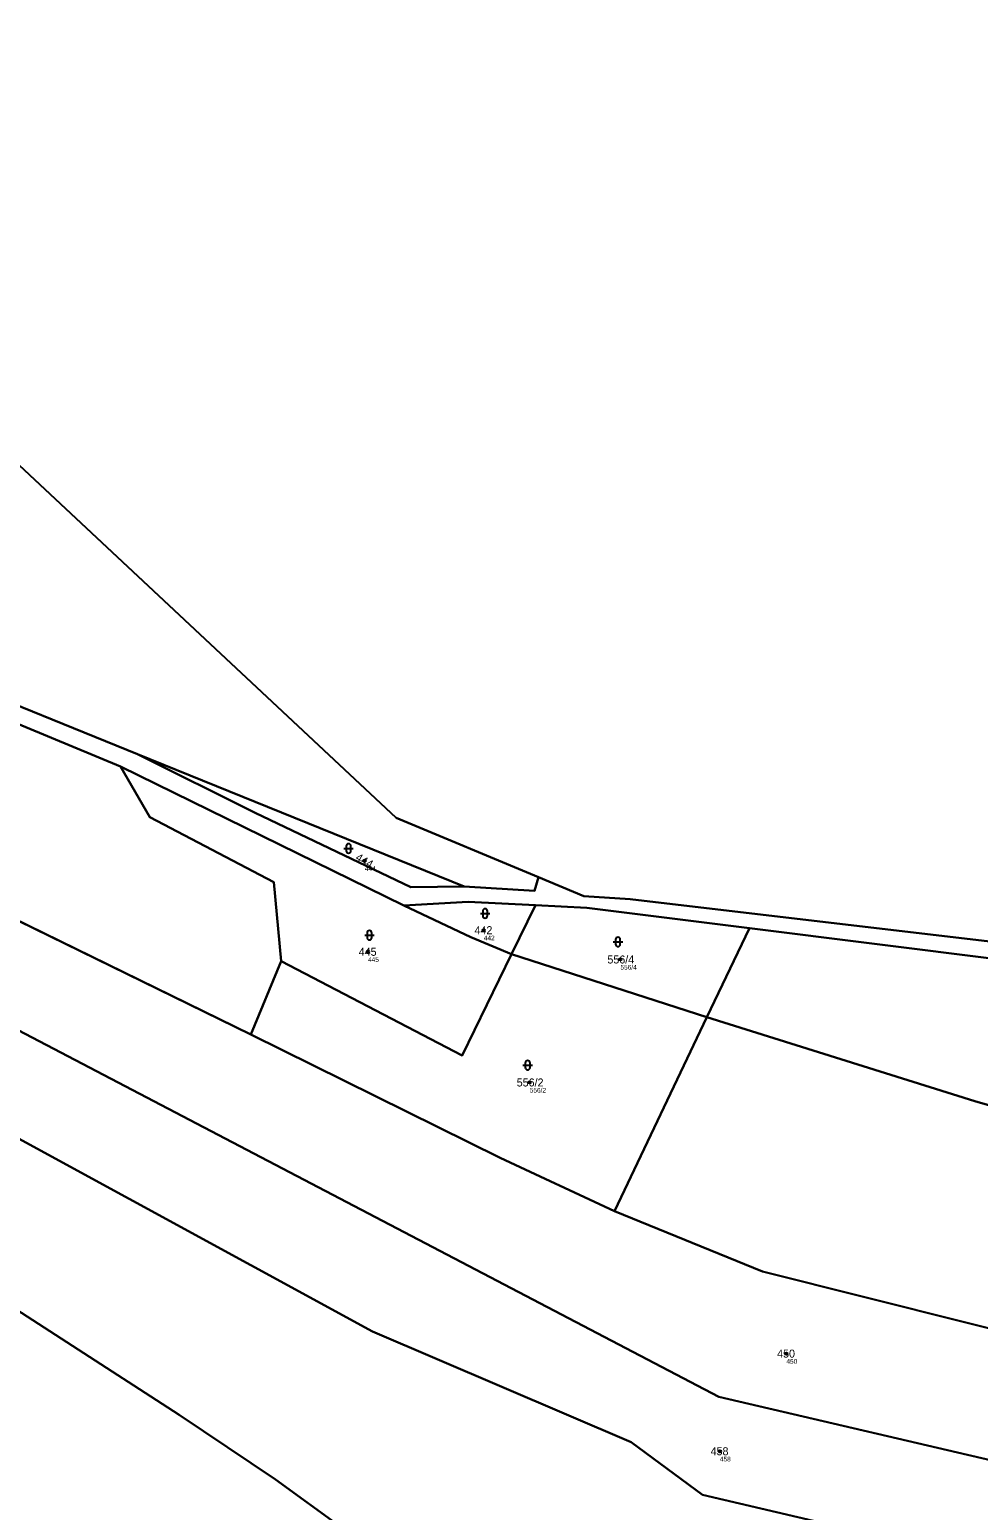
# Model space of a CAD drawing. Extents: x -766177 to -763254, y -1057727 to -1053915.
# Drawn here: x -765094.3 to -764892.9, y -1055503.5 to -1055189 of the extents above; entities that cross this region are included whole.
import ezdxf

# ---------------------------------------------------------------- set-up
doc = ezdxf.new("R2010")
doc.units = 0
for name, color, linetype in [('Vrstva 1', 7, 'Continuous'), ('Vrstva 2', 7, 'Continuous'), ('Vrstva 3', 7, 'Continuous'), ('Vrstva 50', 7, 'Continuous'), ('Vrstva 51', 7, 'Continuous')]:
    doc.layers.add(name, color=color, linetype=linetype)

msp = doc.modelspace()

# ---------------------------------------------------------------- linework, layer by layer
at = {"layer": 'Vrstva 1'}
for p, q in [((-765071.41, -1055342.94), (-765002.04, -1055371.04)), ((-765014.85, -1055375.09), (-765075.02, -1055345.53)), ((-765047.37, -1055402.44), (-765159.08, -1055347.83)), ((-764991.99, -1055385.41), (-764986.9, -1055375.01)), ((-764941.5, -1055379.87), (-764950.52, -1055398.79)), ((-764888.42, -1055386.56), (-764941.5, -1055379.87)), ((-765047.37, -1055402.44), (-765040.94, -1055386.85)), ((-764950.52, -1055398.79), (-764991.99, -1055385.41)), ((-764950.52, -1055398.79), (-764970.17, -1055440.01))]:
    msp.add_line(p, q, dxfattribs=at)
for points in [[(-764986.29, -1055369.06), (-765016.52, -1055356.43), (-765143.75, -1055237.44), (-765170.76, -1055189.03), (-765184.5, -1055172.38), (-765231.58, -1055139.36), (-765234.73, -1055135.28)], [(-764986.29, -1055369.06), (-764976.69, -1055373.07), (-764966.84, -1055373.68), (-764889.25, -1055382.83), (-764853.72, -1055377.3), (-764836.18, -1055369.38), (-764807.82, -1055352.16), (-764775.46, -1055335.75), (-764743.7, -1055324.71), (-764709.55, -1055320.26), (-764653.85, -1055301.47), (-764629.24, -1055298.84), (-764551.53, -1055278.17), (-764464.27, -1055256.83), (-764428.59, -1055244.07), (-764351.18, -1055228.58), (-764323.83, -1055218.78), (-764312.5, -1055208.03), (-764270.81, -1055152.22)], [(-765222.34, -1055253.9), (-765204.91, -1055262.89), (-765164.76, -1055294.86), (-765151.56, -1055297.73), (-765111.93, -1055326.52), (-765071.41, -1055342.94)], [(-765075.02, -1055345.53), (-765115.26, -1055328.82), (-765152.69, -1055301.94)], [(-765071.41, -1055342.94), (-765046.44, -1055355.41), (-765013.41, -1055371.14), (-765002.04, -1055371.04)], [(-765075.02, -1055345.53), (-765068.82, -1055356.3), (-765042.51, -1055370.1), (-765040.94, -1055386.85)], [(-765160.62, -1055368.14), (-764948, -1055479.38), (-764883.67, -1055494.44), (-764811.91, -1055508.77), (-764753.73, -1055525)], [(-765002.04, -1055371.04), (-764987.12, -1055371.96), (-764986.29, -1055369.06)], [(-764986.9, -1055375.01), (-765001.24, -1055374.3), (-765014.85, -1055375.09)], [(-765014.85, -1055375.09), (-765000.68, -1055381.77), (-764991.99, -1055385.41)], [(-764941.5, -1055379.87), (-764976.01, -1055375.55), (-764986.9, -1055375.01)], [(-765040.94, -1055386.85), (-765002.5, -1055406.89), (-764991.99, -1055385.41)], [(-765150.71, -1055395.09), (-765021.52, -1055465.51), (-764966.65, -1055489.05), (-764951.49, -1055500.21), (-764771.73, -1055542.36), (-764763.19, -1055547.21)], [(-764730.92, -1055455.55), (-764829.15, -1055435.06), (-764893.68, -1055416.62), (-764950.52, -1055398.79)], [(-764970.17, -1055440.01), (-764994.42, -1055428.64), (-765047.37, -1055402.44)], [(-764743.22, -1055501.86), (-764938.76, -1055452.8), (-764970.17, -1055440.01)], [(-765110.33, -1055452.36), (-765062.6, -1055483.25), (-765042.11, -1055496.97), (-765013.65, -1055517.61)]]:
    msp.add_lwpolyline(points, dxfattribs=at)
at = {"layer": 'Vrstva 3'}
for p, q in [((-765027.621, -1055362.941), (-765025.619, -1055362.941)), ((-765027.121, -1055362.441), (-765027.121, -1055363.442)), ((-765026.119, -1055363.442), (-765026.119, -1055362.441)), ((-764998.621, -1055376.731), (-764996.619, -1055376.731)), ((-764998.121, -1055376.231), (-764998.121, -1055377.232)), ((-764997.119, -1055377.232), (-764997.119, -1055376.231)), ((-765023.171, -1055381.381), (-765021.169, -1055381.381)), ((-765022.671, -1055380.881), (-765022.671, -1055381.882)), ((-765021.669, -1055381.882), (-765021.669, -1055380.881)), ((-764970.421, -1055382.791), (-764968.419, -1055382.791)), ((-764969.921, -1055382.291), (-764969.921, -1055383.292)), ((-764968.919, -1055383.292), (-764968.919, -1055382.291)), ((-764989.591, -1055408.991), (-764987.589, -1055408.991)), ((-764989.091, -1055408.491), (-764989.091, -1055409.492)), ((-764988.089, -1055409.492), (-764988.089, -1055408.491))]:
    msp.add_line(p, q, dxfattribs=at)
for centre, start, end in [((-765026.62, -1055362.4409), 0, 180), ((-765026.62, -1055363.4409), 180, 359.9878861), ((-764997.62, -1055376.2309), 0, 180), ((-764997.62, -1055377.2309), 180, 359.9878861), ((-765022.17, -1055380.8809), 0, 180), ((-765022.17, -1055381.8809), 180, 359.9878861), ((-764969.42, -1055382.2909), 0, 180), ((-764969.42, -1055383.2909), 180, 359.9878861), ((-764988.59, -1055408.4909), 0, 180), ((-764988.59, -1055409.4909), 180, 359.9878861)]:
    msp.add_arc(centre, 0.5, start, end, dxfattribs=at)
at = {"layer": 'Vrstva 50'}
for centre in [(-765023.16, -1055365.55994), (-764997.9, -1055380.29994), (-765022.48, -1055384.88994), (-764968.89, -1055386.51994), (-764988.14, -1055412.63994), (-764933.66, -1055470.22994), (-764947.78, -1055490.96994)]:
    msp.add_circle(centre, 0.25, dxfattribs=at)
at = {"layer": 'Vrstva 51'}
for points in [[(-764987.12, -1055371.96), (-764986.29, -1055369.06), (-765016.52, -1055356.43), (-765143.75, -1055237.44), (-765170.76, -1055189.03), (-765184.5, -1055172.38), (-765231.58, -1055139.36), (-765234.73, -1055135.28), (-765294.18, -1055171.69), (-765271.93, -1055205.33), (-765257.2, -1055223.42), (-765222.34, -1055253.9), (-765204.91, -1055262.89), (-765164.76, -1055294.86), (-765151.56, -1055297.73), (-765111.93, -1055326.52), (-765071.41, -1055342.94), (-765002.04, -1055371.04)], [(-765115.26, -1055328.82), (-765152.69, -1055301.94), (-765158.56, -1055341.76), (-765159.08, -1055347.83), (-765047.37, -1055402.44), (-765040.94, -1055386.85), (-765042.51, -1055370.1), (-765068.82, -1055356.3), (-765075.02, -1055345.53)], [(-765071.41, -1055342.94), (-765046.44, -1055355.41), (-765013.41, -1055371.14), (-765002.04, -1055371.04)], [(-765014.85, -1055375.09), (-765075.02, -1055345.53), (-765068.82, -1055356.3), (-765042.51, -1055370.1), (-765040.94, -1055386.85), (-765002.5, -1055406.89), (-764991.99, -1055385.41), (-765000.68, -1055381.77)], [(-764743.22, -1055501.86), (-764938.76, -1055452.8), (-764970.17, -1055440.01), (-764994.42, -1055428.64), (-765047.37, -1055402.44), (-765159.08, -1055347.83), (-765160.62, -1055368.14), (-764948, -1055479.38), (-764883.67, -1055494.44), (-764811.91, -1055508.77), (-764753.73, -1055525)], [(-765021.52, -1055465.51), (-764966.65, -1055489.05), (-764951.49, -1055500.21), (-764771.73, -1055542.36), (-764763.19, -1055547.21), (-764753.73, -1055525), (-764811.91, -1055508.77), (-764883.67, -1055494.44), (-764948, -1055479.38), (-765160.62, -1055368.14), (-765161.73, -1055382.7), (-765154.68, -1055387.18), (-765151.44, -1055392.72), (-765150.71, -1055395.09)], [(-764986.9, -1055375.01), (-765001.24, -1055374.3), (-765014.85, -1055375.09), (-765000.68, -1055381.77), (-764991.99, -1055385.41)], [(-764976.01, -1055375.55), (-764986.9, -1055375.01), (-764991.99, -1055385.41), (-764950.52, -1055398.79), (-764941.5, -1055379.87)], [(-764730.92, -1055455.55), (-764713.26, -1055431.04), (-764841.55, -1055400.97), (-764888.42, -1055386.56), (-764941.5, -1055379.87), (-764950.52, -1055398.79), (-764893.68, -1055416.62), (-764829.15, -1055435.06)], [(-764950.52, -1055398.79), (-764991.99, -1055385.41), (-765002.5, -1055406.89), (-765040.94, -1055386.85), (-765047.37, -1055402.44), (-764994.42, -1055428.64), (-764970.17, -1055440.01)], [(-764903.01, -1055588.69), (-764809.7, -1055612.56), (-764805.97, -1055607.73), (-764779.33, -1055585.09), (-764763.19, -1055547.21), (-764771.73, -1055542.36), (-764951.49, -1055500.21), (-764966.65, -1055489.05), (-765021.52, -1055465.51), (-765150.71, -1055395.09), (-765140.42, -1055428.53), (-765110.33, -1055452.36), (-765062.6, -1055483.25), (-765042.11, -1055496.97), (-765013.65, -1055517.61), (-764991.48, -1055541.73), (-764962.27, -1055567.03), (-764925.71, -1055587.46)], [(-764737.26, -1055474.44), (-764730.92, -1055455.55), (-764829.15, -1055435.06), (-764893.68, -1055416.62), (-764950.52, -1055398.79), (-764970.17, -1055440.01), (-764938.76, -1055452.8), (-764743.22, -1055501.86)], [(-764917.06, -1055711.83), (-764910.86, -1055706.2), (-764991.37, -1055637.93), (-765041.12, -1055553.95), (-765019.38, -1055529.01), (-765013.65, -1055517.61), (-765042.11, -1055496.97), (-765062.6, -1055483.25), (-765110.33, -1055452.36), (-765126.57, -1055489.53), (-765049.17, -1055591.02), (-764946.91, -1055733.8), (-764929.13, -1055719.16)]]:
    msp.add_lwpolyline(points, close=True, dxfattribs=at)
for points in [[(-765170.76, -1055189.03), (-765143.75, -1055237.44), (-765016.52, -1055356.43), (-764986.29, -1055369.06), (-764976.69, -1055373.07), (-764966.84, -1055373.68), (-764889.25, -1055382.83), (-764853.72, -1055377.3), (-764836.18, -1055369.38), (-764807.82, -1055352.16), (-764775.46, -1055335.75), (-764743.7, -1055324.71), (-764709.55, -1055320.26), (-764653.85, -1055301.47), (-764629.24, -1055298.84), (-764551.53, -1055278.17), (-764464.27, -1055256.83), (-764428.59, -1055244.07), (-764351.18, -1055228.58), (-764323.83, -1055218.78), (-764312.5, -1055208.03), (-764270.81, -1055152.22)], [(-764629.24, -1055298.84), (-764653.85, -1055301.47), (-764709.55, -1055320.26), (-764743.7, -1055324.71), (-764775.46, -1055335.75), (-764807.82, -1055352.16), (-764836.18, -1055369.38), (-764853.72, -1055377.3), (-764889.25, -1055382.83), (-764966.84, -1055373.68), (-764976.69, -1055373.07), (-764986.29, -1055369.06), (-764987.12, -1055371.96), (-765002.04, -1055371.04), (-765013.41, -1055371.14), (-765046.44, -1055355.41), (-765071.41, -1055342.94), (-765111.93, -1055326.52), (-765151.56, -1055297.73), (-765164.76, -1055294.86), (-765204.91, -1055262.89), (-765222.34, -1055253.9), (-765243.51, -1055242.99), (-765239.4, -1055248.85)], [(-765239.4, -1055248.85), (-765219.77, -1055259.01), (-765209.83, -1055264.15), (-765165.92, -1055299.38), (-765153.7, -1055301.38), (-765152.69, -1055301.94), (-765115.26, -1055328.82), (-765075.02, -1055345.53), (-765014.85, -1055375.09), (-765001.24, -1055374.3), (-764986.9, -1055375.01), (-764976.01, -1055375.55), (-764941.5, -1055379.87), (-764888.42, -1055386.56)]]:
    msp.add_lwpolyline(points, dxfattribs=at)

# ---------------------------------------------------------------- texts
at = {"layer": 'Vrstva 2'}
msp.add_text('444', height=1.699998, rotation=329.9999972, dxfattribs=at).set_placement((-765025.295, -1055365.308))
for s, p in [('442', (-764999.874, -1055381.15)), ('445', (-765024.454, -1055385.74)), ('556/4', (-764971.663, -1055387.37)), ('556/2', (-764990.913, -1055413.49)), ('450', (-764935.634, -1055471.08)), ('458', (-764949.754, -1055491.82))]:
    msp.add_text(s, height=1.699998, dxfattribs=at).set_placement(p)
at = {"layer": 'Vrstva 50'}
for s, p in [('444', (-765023.16, -1055367.716)), ('442', (-764997.9, -1055382.456)), ('445', (-765022.48, -1055387.046)), ('556/4', (-764968.89, -1055388.676)), ('556/2', (-764988.14, -1055414.796)), ('450', (-764933.66, -1055472.386)), ('458', (-764947.78, -1055493.126))]:
    msp.add_text(s, height=0.999996, dxfattribs=at).set_placement(p)

doc.saveas('drawing.dxf')
